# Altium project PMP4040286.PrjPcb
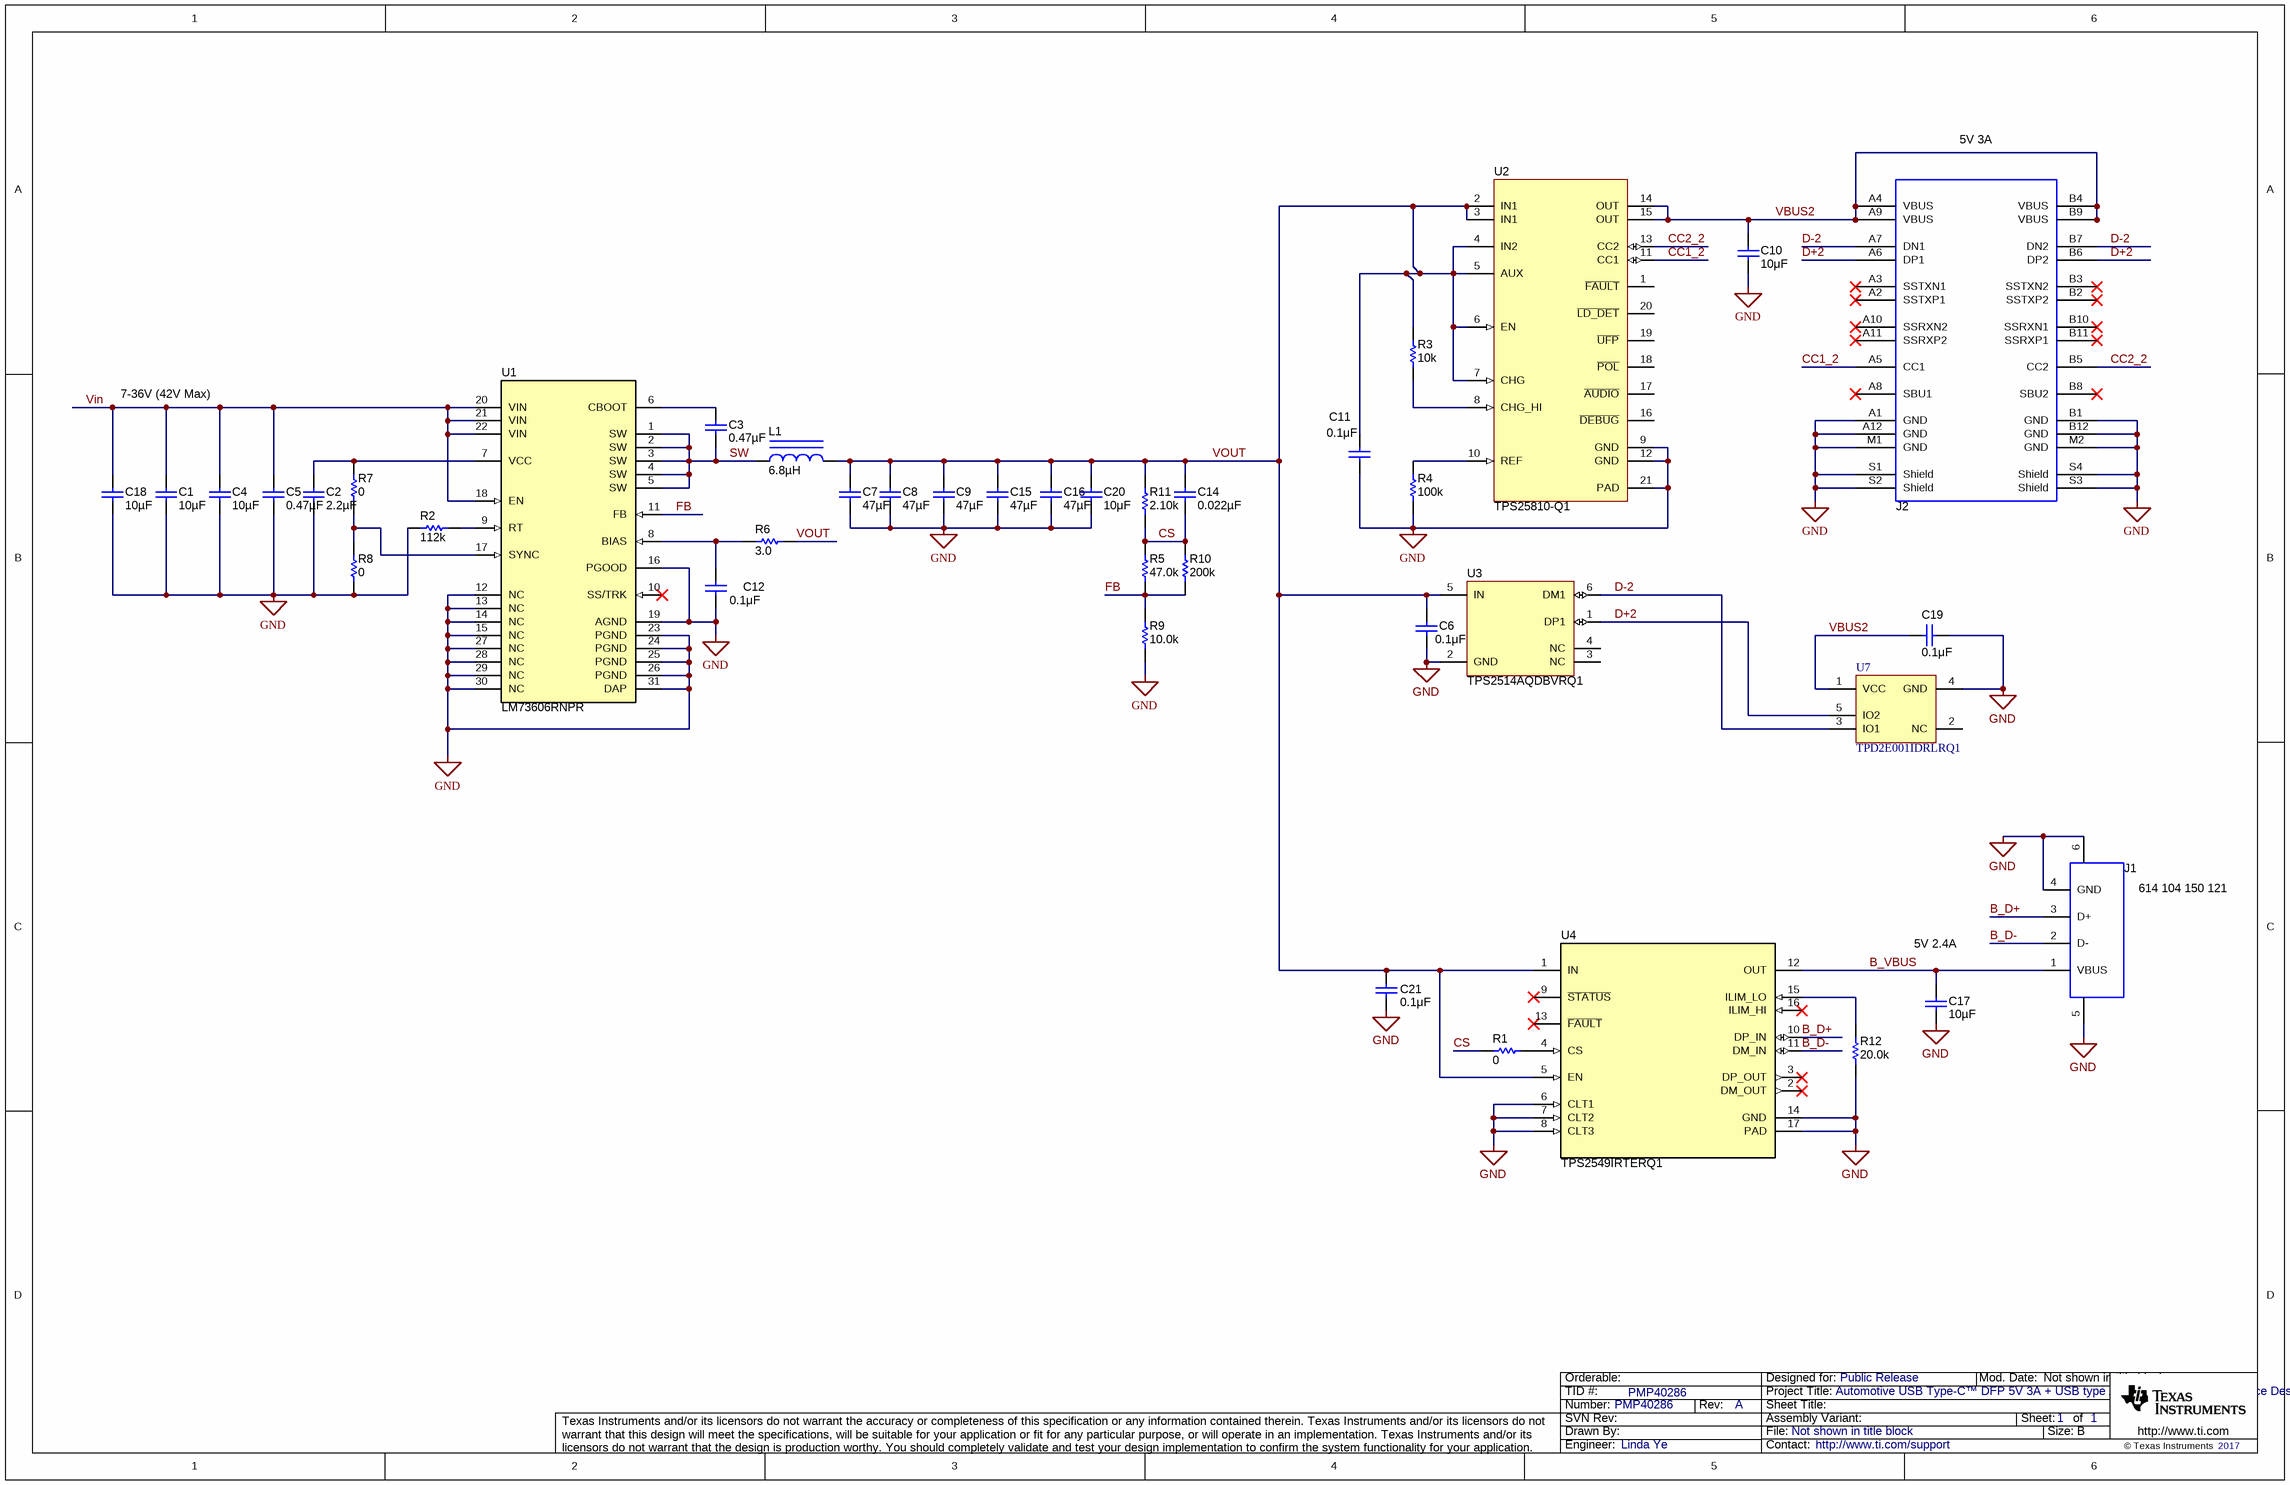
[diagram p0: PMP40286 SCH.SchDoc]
CopyrightYear: 2017; PCB_Layout: Linda Ye; PCB_Rev: A; PRJ_Customer: Public Release; PRJ_Engineer: Linda Ye; PRJ_Number: PMP40286; PRJ_Title: Automotive USB Type-C™ DFP 5V 3A + USB type A 5V 2.4A Charger Reference Design; SCH_Rev: A; TechSupport: http://www.ti.com/support; TID: PMP40286
1 sheet, 40 parts. Net scope: global (net labels, ports and power ports of the same name join across sheets).
Board file: PMP40286 PCB_TID.PcbDoc

## Sheet PMP40286 SCH.SchDoc
size 431 x 279 mm; Date: Not shown in title block; ApprovedBy: Not shown in title block; CheckedBy: Not shown in title block; Author: Not shown in title block; CompanyName: Not shown in title block; Engineer: Not shown in title block; Organization: Not shown in title block; Address1: Not shown in title block; Address2: Not shown in title block; Address3: Not shown in title block; Address4: Not shown in title block; DocumentNumber: 2; Revision: Use project parameter SCH_Rev; SheetNumber: 1; SheetTotal: 1; PageSetup: Record=PageOptions¦CenterHorizontal=True¦CenterVertical=True¦PrintScale=1.00¦XCorrection=1.00¦YCorrection=1.00¦PrintKind=0¦BorderSize=5000000¦LeftOffset=0¦BottomOffset=0¦Orientation=2¦PaperLength=1000¦PaperWidth=1000¦Scale=100¦PaperSource=15¦PrintQuality=600¦MediaType=1¦DitherType=10¦PaperKind=Letter¦PrintScaleMode=1

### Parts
C1  ValueDisplayed: 10µF  [1210]  (hidden comment: GRM32ER71H106KA12L)
C2  ValueDisplayed: 2.2µF  [0603]  (hidden comment: GRM188R61A225KE34D)
C3  ValueDisplayed: 0.47µF  [0603]  (hidden comment: GRM188R71A474KA61D)
C4  ValueDisplayed: 10µF  [1210]  (hidden comment: GRM32ER71H106KA12L)
C5  ValueDisplayed: 0.47µF  [0603]  (hidden comment: C1608X7R1H474K080AC)
C6  ValueDisplayed: 0.1μF  [0603]  (hidden comment: 06033C104JAT2A)
C7  ValueDisplayed: 47µF  [0805_HV]  (hidden comment: GRM21BR61A476ME15)
C8  ValueDisplayed: 47µF  [0805_HV]  (hidden comment: GRM21BR61A476ME15)
C9  ValueDisplayed: 47µF  [0805_HV]  (hidden comment: GRM21BR61A476ME15)
C10  ValueDisplayed: 10μF  [0805_HV]  (hidden comment: C0805C106K8PACTU)
C11  ValueDisplayed: 0.1μF  [0603]  (hidden comment: C1608X7R1E104K)
C12  ValueDisplayed: 0.1μF  [0603]  (hidden comment: C1608X7R1E104K)
C14  ValueDisplayed: 0.022µF  [0603]  (hidden comment: C0603C223K5RACTU)
C15  ValueDisplayed: 47µF  [0805_HV]  (hidden comment: GRM21BR61A476ME15)
C16  ValueDisplayed: 47µF  [0805_HV]  (hidden comment: GRM21BR61A476ME15)
C17  ValueDisplayed: 10µF  [0805_HV]  (hidden comment: GRM219R61A106KE44D)
C18  ValueDisplayed: 10µF  [1210]  (hidden comment: GRM32ER71H106KA12L)
C19  ValueDisplayed: 0.1μF  [0603]  (hidden comment: 06033C104JAT2A)
C20  ValueDisplayed: 10μF  [0805_HV]  (hidden comment: C0805C106K8PACTU)
C21  ValueDisplayed: 0.1μF  [0603]  (hidden comment: C1608X7R1E104K)
J1  614 104 150 121  [WURTH_614104150121]
J2  632 723 300 011  [Wurth_632_723_300_011]  (value not drawn)
L1  ValueDisplayed: 6.8µH  [XAL8080]  (hidden comment: XAL8080-682MEB)
R1  ValueDisplayed: 0  [0603]  (hidden comment: RC0603JR-070RL)
R2  ValueDisplayed: 112k  [0603]
R3  ValueDisplayed: 10k  [0603]  (hidden comment: CRCW060310K0JNEA)
R4  ValueDisplayed: 100k  [0603]  (hidden comment: RC0603FR-07100KL)
R5  ValueDisplayed: 47.0k  [0603]  (hidden comment: RC0603FR-0747KL)
R6  ValueDisplayed: 3.0  [0603]  (hidden comment: CRCW06033R00JNEA)
R7  ValueDisplayed: 0  [0603]  (hidden comment: CRCW06030000Z0EA)
R8  ValueDisplayed: 0  [0603]  (hidden comment: CRCW06030000Z0EA)
R9  ValueDisplayed: 10.0k  [0603]  (hidden comment: CRCW060310K0FKEA)
R10  ValueDisplayed: 200k  [0603]  (hidden comment: RC0603FR-07200KL)
R11  ValueDisplayed: 2.10k  [0603]  (hidden comment: RC0603FR-072K1L)
R12  ValueDisplayed: 20.0k  [0603]  (hidden comment: RT0603BRD0720KL)
U1  LM73606RNPR  [RNP0030A]
U2  TPS25810-Q1  [RVC0020A]
U3  TPS2514AQDBVRQ1  [DBV0006A_N]
U4  TPS2549IRTERQ1  [RTE0016C]
U7  TPD2E001IDRLRQ1  [DRL0005A]

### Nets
GND: C1.2 C2.2 C4.2 C5.2 C6.2 C7.2 C8.2 C9.2 C10.2 C11.2 C12.2 C15.2 C16.2 C17.2 C18.2 C19.2 C20.2 C21.2 J1.4(GND) J1.5(Shield) J1.6(Shield) J2.A1(GND) J2.A12(GND) J2.B1(GND) J2.B12(GND) J2.M1(GND) J2.M2(GND) J2.S1(Shield) J2.S2(Shield) J2.S3(Shield) J2.S4(Shield) R2.1 R4.1 R8.2 R9.1 R12.1 U1.12(NC) U1.13(NC) U1.14(NC) U1.15(NC) U1.16(PGOOD) U1.19(AGND) U1.23(PGND) U1.24(PGND) U1.25(PGND) U1.26(PGND) U1.27(NC) U1.28(NC) U1.29(NC) U1.30(NC) U1.31(DAP) U2.9(GND) U2.12(GND) U2.21(PAD) U3.2(GND) U4.6(CLT1) U4.7(CLT2) U4.8(CLT3) U4.14(GND) U4.17(PAD) U7.4(GND)
B_D+: J1.3(D+) U4.10(DP_IN)
B_D-: J1.2(D-) U4.11(DM_IN)
B_VBUS: C17.1 J1.1(VBUS) U4.12(OUT)
CC1_2: J2.A5(CC1) U2.11(CC1)
CC2_2: J2.B5(CC2) U2.13(CC2)
CS: C14.2 R1.2 R5.2 R10.2 R11.2
D+2: J2.A6(DP1) J2.B6(DP2) U3.1(DP1) U7.5(IO2)
D-2: J2.A7(DN1) J2.B7(DN2) U3.6(DM1) U7.3(IO1)
FB: R5.1 R9.2 R10.1 U1.11(FB)
SW: C3.2 L1.1 U1.1(SW) U1.2(SW) U1.3(SW) U1.4(SW) U1.5(SW)
VBUS2: C10.1 C19.1 J2.A4(VBUS) J2.A9(VBUS) J2.B4(VBUS) J2.B9(VBUS) U2.14(OUT) U2.15(OUT) U7.1(VCC)
Vin: C1.1 C4.1 C5.1 C18.1 U1.18(EN) U1.20(VIN) U1.21(VIN) U1.22(VIN)
VOUT: C6.1 C7.1 C8.1 C9.1 C11.1 C14.1 C15.1 C16.1 C20.1 C21.1 L1.2 R3.2 R6.2 R11.1 U2.2(IN1) U2.3(IN1) U2.4(IN2) U2.5(AUX) U2.6(EN) U2.7(CHG) U3.5(IN) U4.1(IN) U4.5(EN)
NetC2_1: C2.1 R7.2 U1.7(VCC)
NetC3_1: C3.1 U1.6(CBOOT)
NetC12_1: C12.1 R6.1 U1.8(BIAS)
NetR1_1: R1.1 U4.4(CS)
NetR2_2: R2.2 U1.9(RT)
NetR3_1: R3.1 U2.8(CHG_HI)
NetR4_2: R4.2 U2.10(REF)
NetR7_1: R7.1 R8.1 U1.17(SYNC)
NetR12_2: R12.2 U4.15(ILIM_LO)

Not connected (* = marked no-connect by the designer): J2 A2(SSTXP1)* A3(SSTXN1)* A8(SBU1)* A10(SSRXN2)* A11(SSRXP2)* B2(SSTXP2)* B3(SSTXN2)* B8(SBU2)* B10(SSRXN1)* B11(SSRXP1)*; U1 10(SS/TRK)*; U2 1(~{FAULT}) 16(~{DEBUG}) 17(~{AUDIO}) 18(~{POL}) 19(~{UFP}) 20(~{LD_DET}); U3 3(NC) 4(NC); U4 2(DM_OUT)* 3(DP_OUT)* 9(~{STATUS})* 13(~{FAULT})* 16(ILIM_HI)*; U7 2(NC)

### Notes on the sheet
- 5V 3A
- 7-36V (42V Max)
- (near C17) 5V 2.4A

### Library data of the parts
C1 C4 C18 = GRM32ER71H106KA12L: CAP, CERM, 10 µF, 50 V, +/- 10%, X7R, 1210; Manufacturer: MuRata; Polarized: N; CompType: Capacitor; Value: 10uF; U/M: EA; Cap_F: 0.00001; Tolerance_%: 10; Value1: Unknown; VDC_V: 50; Value2: 50V; TaMin_C: -55; TaMax_C: 125; AEC Category: Q200
C2 = GRM188R61A225KE34D: CAP, CERM, 2.2 µF, 10 V, +/- 10%, X5R, 0603; Manufacturer: MuRata; Polarized: N; CompType: Capacitor; Value: 2.2uF; U/M: EA; Cap_F: 0.0000022; Tolerance_%: 10; Value1: Unknown; Value2: 10V; TaMin_C: -55; TaMax_C: 85; AEC Category: Q200
C3 = GRM188R71A474KA61D: CAP, CERM, 0.47 µF, 10 V, +/- 10%, X7R, 0603; Manufacturer: MuRata; Polarized: N; CompType: Capacitor; Value: 0.47uF; U/M: EA; Cap_F: 0.00000047; Tolerance_%: 10; Value1: Unknown; Value2: 10V; TaMin_C: -55; TaMax_C: 125; AEC Category: Q200
C5 = C1608X7R1H474K080AC: CAP, CERM, 0.47 µF, 50 V, +/- 10%, X7R, 0603; Manufacturer: TDK; Polarized: N; CompType: Capacitor; Value: 0.47uF; U/M: EA; Cap_F: 0.00000047; Tolerance_%: 10; Value1: Unknown; VDC_V: 50; Value2: 50V; TaMin_C: -55; TaMax_C: 125; AEC Category: Q200
C6 C19 = 06033C104JAT2A: CAP, CERM, 0.1 μF, 25 V, +/- 5%, X7R, 0603; Manufacturer: AVX; Polarized: N; CompType: Capacitor; Value: 0.1uF; U/M: EA; Cap_F: 0.0000001; Tolerance_%: 5; ESR_ohm: 0.05; Value1: 0.05 ohm; VDC_V: 25; Value2: 25V; TaMin_C: -55; TaMax_C: 125
C7-C9 C15 C16 = GRM21BR61A476ME15: CAP, CERM, 47 µF, 10 V, +/- 20%, X5R, 0805; Manufacturer: MuRata; Polarized: N; CompType: Capacitor; Value: 47uF; U/M: EA; Cap_F: 0.000047; Tolerance_%: 20; Value1: Unknown; VDC_V: 10; Value2: 10V; TaMin_C: -55; TaMax_C: 85; Cap_Case: 0805; AEC Category: Q200
C10 C20 = C0805C106K8PACTU: CAP, CERM, 10 μF, 10 V, +/- 10%, X5R, 0805; Manufacturer: Kemet; Polarized: N; CompType: Capacitor; Value: 10uF; U/M: EA; Cap_F: 0.00001; Tolerance_%: 10; ESR_ohm: 0.003; Value1: 0.003 ohm; Value2: 10V; IRMS_A: 11.43; TaMin_C: -55; TaMax_C: 85; Cap_Case: 0805
C11 C12 C21 = C1608X7R1E104K: CAP, CERM, 0.1 μF, 25 V, +/- 10%, X7R, 0603; Manufacturer: TDK; Polarized: N; CompType: Capacitor; Value: 0.1uF; U/M: EA; Cap_F: 0.0000001; Tolerance_%: 10; ESR_ohm: 0.017; Value1: 0.017 ohm; VDC_V: 25; Value2: 25V; TaMin_C: -55; TaMax_C: 125
C14 = C0603C223K5RACTU: CAP, CERM, 0.022 µF, 50 V, +/- 10%, X7R, 0603; Manufacturer: Kemet; Polarized: N; CompType: Capacitor; Value: 0.022uF; U/M: EA; Cap_F: 0.000000022; Tolerance_%: 10; Value1: Unknown; VDC_V: 50; Value2: 50V; TaMin_C: -55; TaMax_C: 125; SizeArea_mm2: 1.28; SizeAreaWB_mm2: 4.68; SizeX_mm: 1.6; SizeY_mm: 0.8; SizeZ_mm: 1; AEC Category: Q200
C17 = GRM219R61A106KE44D: CAP, CERM, 10 µF, 10 V, +/- 10%, X5R, 0805; Manufacturer: MuRata; Polarized: N; CompType: Capacitor; Value: 10uF; U/M: EA; Cap_F: 0.00001; Tolerance_%: 10; ESR_ohm: 0.005; Value1: 0.005 ohm; Value2: 10V; TaMin_C: -55; TaMax_C: 85; Cap_Case: 0805; AEC Category: Q200; SizeArea_mm2: 2.5; SizeAreaWB_mm2: 6.75; SizeX_mm: 2; SizeY_mm: 1.25; SizeZ_mm: 1.45
J1 = 614 104 150 121: Connector, Receptacle, USB Type A, R/A, Bottom Mount TH; Manufacturer: Wurth Elektronik; SymbolCreator: a0412235
J2 = 632 723 300 011: Connector, Receptacle, USB Type C, R/A; Manufacturer: Wurth Elektronik; SymbolCreator: a0412235; Gender: Female; ContactFinish: Gold; Current_A: 3; Voltage_V: 5; Cert_UL: Y
L1 = XAL8080-682meb: Inductor, Shielded, Composite, 6.8 µH, 11.3 A, 0.0132 ohm, SMD; Manufacturer: Coilcraft; Value: 6.8uH; Ind_H: 6.8E-6; Imax_A: 11.3; Irms: 11.3A @ 40C rise; Isat: 14.13A @ 30% inductance drop; DCR_ohm: 0.0132; Value2: 11.3A; AEC Category: Q200; AEC Qualified: N; SizeAreaWB_mm2: 107.06; SizeArea_mm2: 69.66; SizeX_mm: 8.1; SizeY_mm: 8.6; SizeZ_mm: 8
R1 = RC0603JR-070RL: RES, 0, 5%, 0.1 W, 0603; Manufacturer: Yageo America; CompType: Resistor; Value: 0; Value_Code: 0000; Tolerance_%: 5; Power_W: 0.1; Value2: 0.1W; VDC_V: 50; TempCo: 200 ppm/C; EIA_Code: E24; U/M: EA; AEC Category: Q200; SizeArea_mm2: 1.28; SizeX_mm: 1.6; SizeY_mm: 0.8; SizeZ_mm: 1
R2 = RT0603BRD0719K1L: RES, 112k, 1%, 0.1 W, 0603; Manufacturer: Yageo America; CompType: Resistor; Value: 19.1k; Res_ohm: 19100; Tolerance_%: 0.1; Value1: 0.1%; Value2: 0.1W; VDC_V: 75; EIA_Code: E192; U/M: EA; AEC Category: Q200
R3 = CRCW060310K0JNEA: RES, 10 k, 5%, 0.1 W, 0603; Manufacturer: Vishay-Dale; CompType: Resistor; Value: 10k; Res_ohm: 10000; Value_Code: 10k0; Tolerance_%: 5; Power_W: 0.1; Value2: 0.1W; VDC_V: 75; TempCo: 200 ppm/C; EIA_Code: E24; U/M: EA
R4 = RC0603FR-07100KL: RES, 100 k, 1%, 0.1 W, 0603; Manufacturer: Yageo America; CompType: Resistor; Value: 100k; Res_ohm: 100000; Tolerance_%: 1; Power_W: 0.1; Value2: 0.1W; VDC_V: 150; TempCo: 200 ppm/C; EIA_Code: E96; U/M: EA; SizeArea_mm2: 1.28; SizeX_mm: 1.6; SizeY_mm: 0.8; AEC Category: Q200
R5 = RC0603FR-0747KL: RES, 47.0 k, 1%, 0.1 W, 0603; Manufacturer: Yageo America; CompType: Resistor; Value: 47.0k; Res_ohm: 47000; Value_Code: 47k0; Tolerance_%: 1; Power_W: 0.1; Value2: 0.1W; VDC_V: 150; TempCo: 200 ppm/C; SizeArea_mm2: 1.28; SizeX_mm: 1.6; SizeY_mm: 0.8; U/M: EA; AEC Category: Q200
R6 = CRCW06033R00JNEA: RES, 3.0, 5%, 0.1 W, 0603; Manufacturer: Vishay-Dale; CompType: Resistor; Value: 3.0; Res_ohm: 3; Value_Code: 3R00; Tolerance_%: 5; Power_W: 0.1; Value2: 0.1W; VDC_V: 75; TempCo: 200 ppm/C; SizeArea_mm2: 1.28; SizeX_mm: 1.6; SizeY_mm: 0.8; SizeZ_mm: 1; EIA_Code: E24; U/M: EA; AEC Category: Q200
R7 R8 = CRCW06030000Z0EA: RES, 0, 5%, 0.1 W, 0603; Manufacturer: Vishay-Dale; CompType: Resistor; Value: 0; Value_Code: 0000; Tolerance_%: 5; Power_W: 0.1; Value2: 0.1W; VDC_V: 75; TempCo: 200 ppm/C; SizeArea_mm2: 1.28; SizeX_mm: 1.6; SizeY_mm: 0.8; SizeZ_mm: 1; EIA_Code: E24; U/M: EA; AEC Category: Q200
R9 = CRCW060310K0FKEA: RES, 10.0 k, 1%, 0.1 W, 0603; Manufacturer: Vishay-Dale; CompType: Resistor; Value: 10.0k; Res_ohm: 10000; Value_Code: 10k0; Tolerance_%: 1; Power_W: 0.1; Value2: 0.1W; VDC_V: 75; TempCo: 100 ppm/C; SizeArea_mm2: 1.28; SizeX_mm: 1.6; SizeY_mm: 0.8; EIA_Code: E96; U/M: EA; AEC Category: Q200
R10 = RC0603FR-07200KL: RES, 200 k, 1%, 0.1 W, 0603; Manufacturer: Yageo America; CompType: Resistor; Value: 200k; Res_ohm: 200000; Tolerance_%: 1; Power_W: 0.1; Value2: 0.1W; VDC_V: 150; TempCo: 200 ppm/C; SizeArea_mm2: 1.28; SizeX_mm: 1.6; SizeY_mm: 0.8; EIA_Code: E96; U/M: EA; AEC Category: Q200
R11 = RC0603FR-072K1L: RES, 2.10 k, 1%, 0.1 W, 0603; Manufacturer: Yageo America; CompType: Resistor; Value: 2.10k; Res_ohm: 2100; Value_Code: 2k10; Tolerance_%: 1; Power_W: 0.1; Value2: 0.1W; VDC_V: 150; TempCo: 200 ppm/C; EIA_Code: E96; U/M: EA; AEC Category: Q200; SizeArea_mm2: 1.28; SizeX_mm: 1.6; SizeY_mm: 0.8
R12 = RT0603BRD0720KL: RES, 20.0 k, 0.1%, 0.1 W, 0603; Manufacturer: Yageo America; CompType: Resistor; Value: 20.0k; Res_ohm: 20000; Value_Code: 20k0; Tolerance_%: 0.1; Value2: 0.1W; VDC_V: 75; TempCo: 25 ppm/C; EIA_Code: E192; U/M: EA; AEC Category: Q200; SizeArea_mm2: 1.28; SizeX_mm: 1.6; SizeY_mm: 0.8; SizeZ_mm: 1
U1 = LM73605RNPR: 3.5V to 36V 5A Synchronous Step-Down Voltage Regulator, RNP0030A; Alternate PartNumber: LM73606RNPRT; Manufacturer: Texas Instruments; SymbolCreator: Altium; CompType: IC; U/M: EA
U2 = TPS25810RVC: USB Type-C DFP Controller and Power Switch with Load Detection, RVC0020A; Manufacturer: Texas Instruments; SymbolCreator: Altium; CompType: IC; U/M: EA
U3 = TPS2514ADBV: USB Dedicated Charging Port Controller, DBV0006A; Manufacturer: Texas Instruments; SymbolCreator: a0411947; CompType: IC; U/M: EA
U4 = TPS2549IRTERQ1: USB Charging Port Controller, RTE0016C (WQFN-16); Alternate PartNumber: TPS2549IRTETQ1; Manufacturer: Texas Instruments; SymbolCreator: Altium; SizeArea_mm2: 9; SizeAreaWB_mm2: 16; SizeX_mm: 3; SizeZ_mm: 0.8; CompType: IC; U/M: EA
U7 = TPD2E001DRLRG4: Low-Capacitance + / - 15 kV ESD-Protection Array for High-Speed Data Interfaces, 2 Channels, 5-pin SOT (DRL), Green (RoHS & no Sb/Br); Manufacturer: Texas Instruments; Alternate Manufacturer: None; Alternate PartNumber: Equivalent; Breakdown Voltage(Min)(V): 11; IEC 61000-4-2 Air-Gap(+/- kV): 15; IEC 61000-4-2 Contact(+/- kV): 8; IO Capacitance(Typ)(pF): 1.5; IO Leakage Current(nA): 1; SubFamily: ESD Solution; USB High Speed: TRUE

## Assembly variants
001: not fitted R7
